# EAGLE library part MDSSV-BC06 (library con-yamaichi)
YAMAICHI CONNECTOR
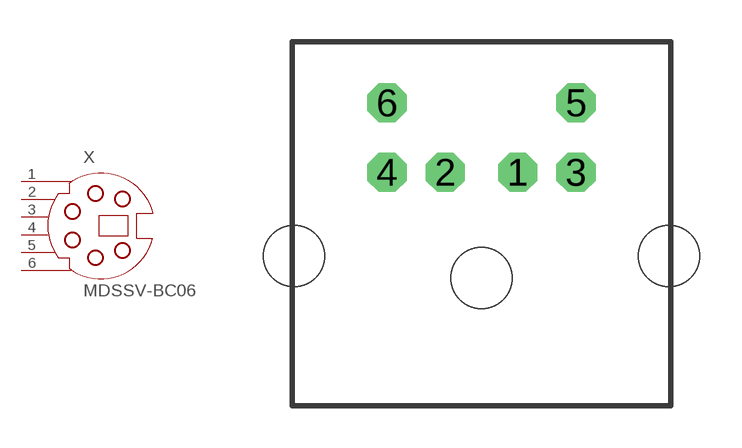
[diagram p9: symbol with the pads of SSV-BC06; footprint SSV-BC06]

Designator prefix X

## MDSSV-BC06 (OC_FARNELL: unknown; OC_NEWARK: unknown)  [SSV-BC06]
1  1  pas
2  2  pas
3  3  pas
4  4  pas
5  5  pas
6  6  pas

## Footprint SSV-BC06 (pad centres in mm)
Mini Din YAMAICHI CONNECTOR
drill 0.9 octagon: 1 1.3,8.5; 2 -1.3,8.5; 3 3.4,8.5; 4 -3.4,8.5; 5 3.4,11; 6 -3.4,11
hole 2.2 at -6.75,5.5
hole 2.2 at 0,4.7
hole 2.2 at 6.75,5.5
